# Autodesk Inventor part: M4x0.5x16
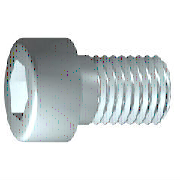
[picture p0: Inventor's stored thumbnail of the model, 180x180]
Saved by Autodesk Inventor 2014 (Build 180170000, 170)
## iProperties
IsCustomPart: 1
Company: 한국ATC센터
Created: 2009-02
Part Number: M4x0.5x16
Material: 강철, 연강
Description: 6각머리 태핑 나사
Document SubType Name: Modeling
Standard: KS B 1003
Designer: KYOUNG IL JANG
Standards Organization: KS
Language: ko-KR
Size Designation: M 4 x 16
Categories: <MemberInstance><Categories><Category DisplayName="조임쇠" InternalName="e4da775c-781d-43d5-af7c-5136215cf5a6" Mnemonic="FSTN"><Category DisplayName="볼트" InternalN
Density: 7.86 g/cm^3
Mass: 2.62973 g
Surface Area: 3.81118 cm^2
Volume: 0.334572 cm^3
Vendor: CBT Solutions
Appearance: 연마 - 진회색
Author: KYOUNG IL JANG
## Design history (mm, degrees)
sketch "스케치1"
  geometry: L1 (-1, 0)-(16, 0); L2 (16, 0)-(16, 2); L3 (16, 2)-(1.75, 2); L4 (1.75, 2)-(1.32, 2); L5 (1.32, 2)-(0, 2); L6 (0, 2)-(0, 3.5); L7 (0, 3.5)-(-4, 3.5); L8 (-4, 3.5)-(-4, 1.732); L9 (-4, 1.732)-(-2, 1.732); L10 (-2, 1.732)-(-1, 0); L11 (-8, 0)-(20, 0) reference; L12 (0, -0.7)-(0, 4.2) reference; L13 (1.75, 2)-(0, 2)
  constraints: 22 end point, 6 parallel, 2 collinear, 2 perpendicular, 1 horizontal, 1 point on line
  dimensions: "d1" = 14.25 distance from line of L3.end L2 (= GEL); "d2" = 0.42952 distance of L4.end L3.end (computed from GAL); "d3" = 4 distance between parallel lines of L8 L6 (= KOH); "d4" = 2 distance of L8.end L9.end (= INTI); "d5" = 60 deg angle of L10 L1; "d6" = 4 diameter of L3 L1 (= GD); "d7" = 4 diameter of L5 L1 (= BDM); "d8" = 3.4641 diameter of L9 L1 (= 1.1547 x SW); "d9" = 7 diameter of L7 L1 (= KOD); "d26" = 16 distance between parallel lines of L12 L2 (= NLG)
revolve "본체" sketch "스케치1" stored, may be unused: angle "d10" = 90 deg
sketch "스케치2"
  geometry: L1 (0, -4.9)-(0, 4.9) reference; L2 (-4.9, 0)-(4.9, 0) reference; L3 (1.732, 0)-(0.866, -1.5); L4 (0.866, -1.5)-(-0.866, -1.5); L5 (-0.866, -1.5)-(-1.732, 0); L6 (-1.732, 0)-(-0.866, 1.5); L7 (-0.866, 1.5)-(0.866, 1.5); L8 (0.866, 1.5)-(1.732, 0); 2 further points
  constraints: 12 end point, 1 coincident, 1 horizontal alignment, 1 point on line, 12 other
extrude "슬롯" join sketch "스케치2" stored distance "d11" = 10; taper "d12" = 0 deg
workplane "Work Plane1"
fillet "Fillet2" dims "d30" = 0.1 (= R)
body "Solid1"
fillet "모깎기1" dims "d17" = 0.4 (= RR)
feature "스레드" dims "d13" = 14.25 (= GEL), "d14" = 0
chamfer "모따기1" distance "d15" = 0.42941 (= -0.5 x SPD + 0.5 x GD); stored, may be unused: second distance "d16" = 0.42941 (= GUL), angle "d27" = 45 deg
other parameters: "GD" = 4 (= NND) [user parameter; used in 2 equation terms], "NLG" = 16 [user parameter; used in 1 equation term], "GEL" = 14.25 [user parameter; used in 2 equation terms], "KOD" = 7 [user parameter; used in 1 equation term], "KOH" = 4 [user parameter; used in 1 equation term], "INTI" = 2 [user parameter; used in 1 equation term], "GAL" = 0.42941 (= 0.61345 x PTC) [user parameter; used in 1 equation term], "GUL" = 0.42941 (= 0.61345 x PTC) [user parameter; used in 1 equation term], "BDM" = 4 (= NND) [user parameter; used in 1 equation term], "SW" = 3 [user parameter; used in 2 equation terms], "RR" = 0.4 [user parameter; used in 1 equation term], "SPD" = 3.14117 (= NND - 1.2269 x PTC) [user parameter; used in 1 equation term], "d19" = 0, "d28" = 0, "d29" = 0, "R" = 0.1 [user parameter; used in 1 equation term], "PHH" = 0.2 [user parameter], "GD1" = 3.14117 (= THREADDIA - 1.2269 x PTC) [user parameter], "THREADDIA" = 4 [user parameter; used in 1 equation term], "FAWI" = 45 deg [user parameter], "TPU" = 14.28571 (computed from PTC) [user parameter], "PTC" = 0.7 [user parameter; used in 5 equation terms], "NND" = 4 [user parameter; used in 3 equation terms], "TOA" = 30 deg [user parameter], "E0" = 3.465 (= 1.155 x SW) [user parameter]
